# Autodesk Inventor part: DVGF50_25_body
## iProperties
Created: 2010-04
Part Number: DVGF50_25_body
Document SubType Name: Modeling
Designer: TB
Mass: 548.636 g
Surface Area: 1083.4 cm^2
Volume: 548.636 cm^3
Density: 1 g/cm^3
Author: TB
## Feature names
1. Kropp [Revolution]
2. Chamfer
3. Extrusion2
4. Hole1
5. Revolution2
6. Hole2
7. Fillet1
8. Extrusion3
9. Hole3
